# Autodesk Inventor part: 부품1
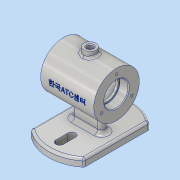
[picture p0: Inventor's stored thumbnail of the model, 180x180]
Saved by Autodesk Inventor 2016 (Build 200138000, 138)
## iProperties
Created: 2017-12
Part Number: 부품1
Material: 알루미늄 6061
Document SubType Name: Modeling
Designer: 605-07
Density: 2.7 g/cm^3
Appearance: 알루미늄 - 평지
Mass: 465.968 g
Surface Area: 486.468 cm^2
Volume: 172.581 cm^3
Author: 605-07
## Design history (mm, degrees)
sketch "스케치1"
  geometry: L1 (35, 0)-(-35, 0); L2 (35, 30)-(-35, 30); L3 (-35, 30)-(-35, 16); L4 (-35, 16)-(-23, 16); L5 (-23, 16)-(-23, 14); L6 (-23, 14)-(-20, 14); L7 (-20, 14)-(-20, 25); L8 (-20, 25)-(20, 25); L9 (20, 25)-(20, 14); L10 (20, 14)-(23, 14); L11 (23, 14)-(23, 16); L12 (23, 16)-(35, 16); L13 (35, 16)-(35, 30); 1 further point
  constraints: 26 end point, 8 perpendicular, 3 horizontal, 1 midpoint, 1 vertical, 1 vertical alignment
  dimensions: "d1" = 35 distance of L1.start point (0, 0); "d2" = 70 distance of L1.start L1.end; "d3" = 70 distance of L2.start L2.end; "d4" = 12 distance of L3.end L4.end; "d5" = 3 distance of L5.end L6.end; "d7" = 40 distance of L7.end L8.end; "d8" = 3 distance of L9.end L10.end; "d9" = 12 distance of L11.end L12.end; "d10" = 60 diameter of L2 L1; "d11" = 50 diameter of L8 L1; "d12" = 32 diameter of L12 L1; "d13" = 28 diameter of L10 L1; "d14" = 32 diameter of L4 L1; "d15" = 28 diameter of L6 L1
revolve "회전1" sketch "스케치1" stored, may be unused: angle "d16" = 90 deg
node "작업 평면2"
sketch "스케치3"
  geometry: L1 (-35, -42.426)-(35, -42.426); L2 (35, -42.426)-(35, 42.426); L3 (35, 42.426)-(-35, 42.426); L4 (-35, 42.426)-(-35, -42.426); L5 (-35, -42.426)-(35, 42.426); L6 (35, -42.426)-(-35, 42.426); A1 r 55 centre (0, 0) between (-35, -42.426) and (35, -42.426); A2 r 55 centre (0, 0) between (35, 42.426) and (-35, 42.426); 1 further point
  constraints: 12 end point, 4 point on circle, 2 centre point, 2 midpoint, 2 parallel, 1 coincident, 1 horizontal, 1 perpendicular
  dimensions: "d27" = 70 distance of L2.end L3.end; "d28" = 55 radius of A2
extrude "돌출1" join sketch "스케치3" distance "d29" = 10; taper "d30" = 0 deg
sketch "스케치4"
  geometry: L1 (-15, 0)-(15, 0); L2 (-15, -5)-(15, -5); L3 (15, 5)-(-15, 5); A1 r 5 centre (-15, 0) between (-15, 5) and (-15, -5); A2 r 5 centre (15, 0) between (15, -5) and (15, 5); 2 further points
  constraints: 8 end point, 4 point on circle, 4 tangent, 2 centre point, 1 coincident, 1 horizontal, 1 midpoint, 1 parallel
  dimensions: "d31" = 5 radius of A2; "d32" = 30 distance of L3.start L3.end
extrude "돌출2" join sketch "스케치4" stored distance "d33" = 10; taper "d34" = 0 deg
node "작업 평면3"
sketch "스케치5"
  geometry: C1 r 8 at (0, 0); 1 further point
  constraints: 1 centre point, 1 coincident
  dimensions: "d36" = 16 diameter of C1
extrude "돌출3" join sketch "스케치5" stored distance "d37" = 10; taper "d38" = 0 deg
node "작업 평면4"
sketch "스케치6"
  geometry: L1 (-35, 30)-(-35, -30) reference; L2 (35, 30)-(-35, 30) reference; 2 further points
  constraints: 1 other
  dimensions: "d39" = 35 distance from line of L1 point (0, 0); "d40" = 30 distance from line of L2 point (0, 0)
feature "엠보싱1" sketch "스케치6" dims "d1" = 35, "d2" = 70, "d3" = 70, "d4" = 12, "d5" = 3, "d7" = 40, "d8" = 3, "d9" = 12, "d10" = 60, "d11" = 50, "d12" = 32, "d13" = 28, "d14" = 32, "d15" = 28, "d27" = 70, "d28" = 55, "d41" = 0.5, "d42" = 0
fillet "모깎기1" dims "d43" = 3
fillet "모깎기2" dims "d44" = 3
fillet "모깎기3" dims "d45" = 3
sketch "스케치7"
  geometry: L1 (0, 40)-(0, 24); L2 (-5, 40)-(-5, 24); L3 (5, 24)-(5, 40); A1 r 5 centre (0, 40) between (5, 40) and (-5, 40); A2 r 5 centre (0, 24) between (-5, 24) and (5, 24); 2 further points
  constraints: 8 end point, 4 point on circle, 4 tangent, 2 centre point, 1 midpoint, 1 parallel, 1 vertical, 1 vertical alignment
  dimensions: "d46" = 5 radius of A1; "d47" = 16 distance of L3.start L3.end; "d48" = 32 distance of point (0, 0) point (0, 32)
extrude "돌출4" cut sketch "스케치7" stored distance "d49" = 10; taper "d50" = 0 deg
sketch "스케치8" dims "d51" = 46
  geometry: 3 further points
  constraints: 2 horizontal alignment, 1 coincident, 2 other
hole "구멍1" sketch "스케치8" at (-23, 0) diameter "d52" = 3.242; stored, may be unused: countersink angle "d56" = 90 deg, drill point angle "d58" = 120 deg; dims "d53" = 8, "d54" = 4, "d55" = 2, "d57" = 10
hole "구멍2" diameter "d64" = 8; stored, may be unused: countersink angle "d68" = 90 deg, drill point angle "d70" = 0 deg; dims "d62" = 10, "d63" = 10, "d65" = 8, "d66" = 4, "d67" = 2, "d69" = 15.25
chamfer "모따기1" distance "d71" = 1; stored, may be unused: second distance "d72" = 2, angle "d73" = 45 deg
fillet "모깎기4" dims "d74" = 3
fillet "모깎기5" dims "d75" = 0.3
fillet "모깎기6" dims "d76" = 5
node "솔리드1"
mirror "대칭1"
pattern_circular "원형 패턴1" dims angle "d60" = 360 deg
mirror "대칭2"
other parameters: "d23" = -62, "d35" = 37
